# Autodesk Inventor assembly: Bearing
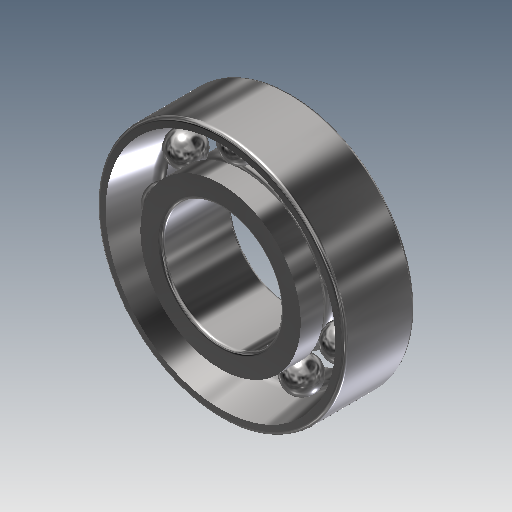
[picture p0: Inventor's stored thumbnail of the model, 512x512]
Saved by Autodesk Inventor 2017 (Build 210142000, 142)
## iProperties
Created: 2019-02
Part Number: Bearing
Document SubType Name: Assembly
Designer: user
Mass: 61.2581 g
Surface Area: 67.9445 cm^2
Volume: 7.80358 cm^3
Density: 7.85 g/cm^3
ClientObjectVersion: 1
Author: user
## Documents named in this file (2)
- C:\Users\user\Documents\EIA\Cursos\Diseño asistido por computador\Clase 7 Dynamic simulation\Ensamble reductor de velocidad\Ensamble\Design Accelerator\Bearing3.iam
- C:\Users\user\Documents\Inventor\Content Center Files\R2017\en-US\BS 292 (II)\BS 292_ Part 1 - 7004 - 20 x 42 x 12.ipt
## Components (1 placed, 1 different names)
1. BS 292: Part 1 (II) - Metric 7004 - 20 x 42 x 12:1
